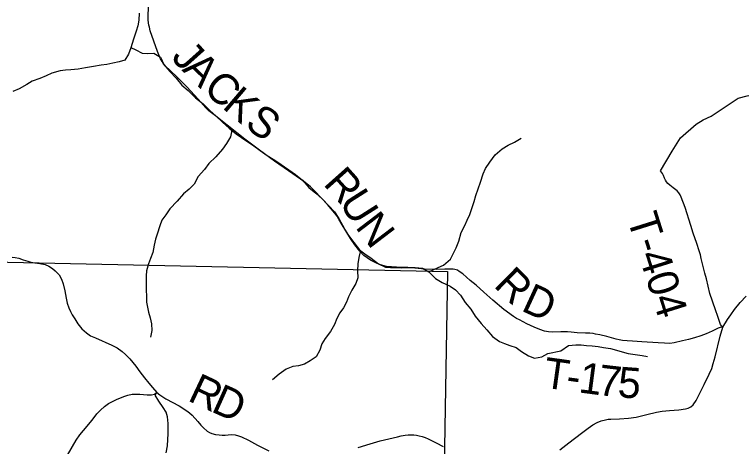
# Model space of a CAD drawing. Extents: x 0 to 34, y 0 to 22.
# Drawn here: x 25.254 to 26.601, y 19.296 to 20.097 of the extents above; entities that cross this region are included whole.
import ezdxf

# ---------------------------------------------------------------- set-up
doc = ezdxf.new("R2010")
doc.units = 0
for name, color, linetype in [('GM_X_Corporation', 7, 'Continuous'), ('GM_X_County_Road', 7, 'Continuous'), ('GM_X_County_Road_Text', 7, 'Continuous'), ('GM_X_Minor_River', 7, 'Continuous'), ('GM_X_State_Route', 7, 'Continuous'), ('GM_X_Township_Road', 7, 'Continuous'), ('GM_X_Township_Road_Text', 7, 'Continuous')]:
    doc.layers.add(name, color=color, linetype=linetype)

msp = doc.modelspace()

# ---------------------------------------------------------------- linework, layer by layer
at = {"layer": 'GM_X_Corporation'}
msp.add_lwpolyline([(25.037, 19.6422), (26.0559, 19.6207), (26.0385, 18.6067), (25.0268, 18.6245)], close=True, dxfattribs=at)
at = {"layer": 'GM_X_County_Road'}
for points in [[(25.2494, 19.6471), (25.2548, 19.6464), (25.2617, 19.6449), (25.2702, 19.6422), (25.2786, 19.6395), (25.2843, 19.6379), (25.2914, 19.6364), (25.301, 19.6355), (25.3105, 19.6335), (25.3175, 19.6306), (25.324, 19.6262), (25.3294, 19.6215), (25.3365, 19.6142), (25.341, 19.6063), (25.3438, 19.5979), (25.347, 19.5845), (25.3494, 19.5709), (25.3515, 19.5619), (25.3545, 19.5532), (25.3576, 19.5462), (25.3608, 19.54), (25.3655, 19.5325), (25.3715, 19.5232), (25.3788, 19.5142), (25.3874, 19.5066), (25.3948, 19.5015), (25.4041, 19.4973), (25.4344, 19.4841), (25.4439, 19.4788), (25.4533, 19.4722), (25.4595, 19.4668), (25.4675, 19.4587), (25.4785, 19.4449), (25.4859, 19.4348), (25.4944, 19.4233), (25.5029, 19.4132), (25.5097, 19.4052), (25.5177, 19.3965), (25.5229, 19.3918), (25.5286, 19.3879), (25.5344, 19.3847), (25.5587, 19.3714), (25.573, 19.3623), (25.5779, 19.3585), (25.5829, 19.354), (25.5932, 19.3426), (25.5993, 19.3355), (25.604, 19.3304), (25.6109, 19.3243), (25.6151, 19.3218), (25.6193, 19.3203), (25.6261, 19.3184), (25.6329, 19.3176), (25.6383, 19.3173), (25.6441, 19.3174), (25.6551, 19.3181), (25.6624, 19.3175), (25.6688, 19.3158), (25.6747, 19.3138), (25.6873, 19.3081), (25.7043, 19.2986), (25.7252, 19.2882)], [(25.8903, 19.2945), (25.9127, 19.3013), (25.9313, 19.3063), (25.9634, 19.3138), (25.9704, 19.3158), (25.9774, 19.317), (25.9832, 19.3178), (25.9889, 19.3178), (25.9935, 19.3176), (25.9983, 19.3169), (26.0036, 19.3159), (26.0092, 19.3146), (26.0147, 19.3128), (26.0204, 19.3103), (26.0278, 19.3069), (26.0351, 19.3027), (26.0478, 19.2961)]]:
    msp.add_lwpolyline(points, dxfattribs=at)
at = {"layer": 'GM_X_Minor_River'}
for points in [[(25.4851, 20.0991), (25.4843, 20.0866), (25.4821, 20.076), (25.4791, 20.0657), (25.4746, 20.0512), (25.4693, 20.0353), (25.4651, 20.0235), (25.458, 20.0121), (25.4477, 20.0094), (25.436, 20.0067), (25.425, 20.0043), (25.4143, 20.0028), (25.4003, 20.0008), (25.3855, 19.9978), (25.3719, 19.9954), (25.3582, 19.9943), (25.3483, 19.9935), (25.3385, 19.9923), (25.3233, 19.9884), (25.3123, 19.9831), (25.3006, 19.9785), (25.2865, 19.9731), (25.2767, 19.9674), (25.2623, 19.959), (25.2509, 19.954)], [(25.4694, 20.0355), (25.4784, 20.0311), (25.4902, 20.0251), (25.4997, 20.0247), (25.5122, 20.0251), (25.5243, 20.0176), (25.5308, 20.0043), (25.5419, 19.9914), (25.5533, 19.9789), (25.5639, 19.9661), (25.5757, 19.9558), (25.5894, 19.9422), (25.6031, 19.9312), (25.6157, 19.9187), (25.6274, 19.9085), (25.6392, 19.8975), (25.6518, 19.8862), (25.6643, 19.8756), (25.6746, 19.8691), (25.6845, 19.8623), (25.697, 19.8533), (25.7092, 19.8446), (25.7217, 19.8355), (25.7362, 19.8268), (25.748, 19.8188), (25.762, 19.809), (25.7742, 19.8003), (25.7875, 19.7897), (25.7993, 19.7765), (25.8118, 19.7659), (25.824, 19.7553), (25.8362, 19.7424), (25.8465, 19.7314), (25.8548, 19.7189), (25.8613, 19.7064), (25.8663, 19.6969), (25.8728, 19.6874), (25.8823, 19.6741), (25.8933, 19.6605), (25.9028, 19.6533), (25.9146, 19.645), (25.9279, 19.6344), (25.9412, 19.6283), (25.9507, 19.628), (25.9609, 19.628), (25.9704, 19.6273), (25.9833, 19.6277), (25.9962, 19.6277), (26.0095, 19.6266), (26.0217, 19.6198), (26.0339, 19.6073), (26.046, 19.5998), (26.0608, 19.593), (26.0711, 19.5866), (26.0802, 19.5767), (26.089, 19.5631), (26.0993, 19.5509), (26.1073, 19.538), (26.1183, 19.524), (26.1286, 19.5123), (26.1396, 19.4997), (26.1522, 19.4907), (26.1617, 19.4873), (26.1716, 19.4835), (26.1833, 19.4797), (26.1928, 19.4722), (26.2058, 19.4642), (26.2175, 19.4601), (26.2308, 19.4624), (26.2422, 19.4685), (26.2657, 19.4732)], [(25.6565, 19.8822), (25.6541, 19.8702), (25.6469, 19.8577), (25.639, 19.847), (25.6269, 19.8333), (25.6136, 19.8207), (25.6057, 19.8093), (25.5943, 19.7967), (25.5868, 19.7826), (25.5777, 19.7731), (25.5667, 19.7647), (25.5554, 19.751), (25.5418, 19.7365), (25.5342, 19.7258), (25.527, 19.7159), (25.5232, 19.7049), (25.5183, 19.69), (25.515, 19.6802), (25.5127, 19.6691), (25.5101, 19.6558), (25.5056, 19.6444), (25.5022, 19.6345), (25.4984, 19.622), (25.4977, 19.6125), (25.4978, 19.5859), (25.4982, 19.5745), (25.4986, 19.5638), (25.5001, 19.5543), (25.502, 19.5448), (25.5051, 19.5346), (25.5074, 19.5232), (25.5082, 19.511), (25.5056, 19.4985)], [(26.0217, 19.6198), (26.0387, 19.6279), (26.0486, 19.6321), (26.0615, 19.6432), (26.0668, 19.6534), (26.072, 19.6641), (26.0769, 19.677), (26.0814, 19.693), (26.0882, 19.7059), (26.0924, 19.7158), (26.0973, 19.7261), (26.1003, 19.7356), (26.1052, 19.7501), (26.1086, 19.7615), (26.1127, 19.774), (26.1169, 19.7858), (26.1221, 19.8014), (26.1267, 19.8113), (26.1342, 19.8231), (26.1444, 19.8365), (26.1573, 19.8479), (26.1687, 19.8548), (26.1801, 19.8601), (26.1926, 19.8678)], [(25.8946, 19.6595), (25.8918, 19.6464), (25.89, 19.6346), (25.8893, 19.6217), (25.8897, 19.6088), (25.8863, 19.5981), (25.8791, 19.5859), (25.8727, 19.5734), (25.8689, 19.5639), (25.8633, 19.5532), (25.8568, 19.5437), (25.8508, 19.5334), (25.8466, 19.522), (25.8395, 19.509), (25.8293, 19.4961), (25.8232, 19.4862), (25.8198, 19.4748), (25.8126, 19.4626), (25.8013, 19.4546), (25.7914, 19.4488), (25.7801, 19.4458), (25.7694, 19.4442), (25.7573, 19.4396), (25.7444, 19.4301), (25.7319, 19.4198)], [(26.2657, 19.4732), (26.28, 19.4832), (26.2936, 19.4848), (26.3038, 19.4846), (26.3133, 19.4832), (26.3239, 19.4829), (26.3349, 19.4812), (26.3451, 19.4798), (26.358, 19.4777), (26.369, 19.4748), (26.3796, 19.4715), (26.3906, 19.4686), (26.4039, 19.4665), (26.4164, 19.4648), (26.4266, 19.463)]]:
    msp.add_lwpolyline(points, dxfattribs=at)
at = {"layer": 'GM_X_State_Route'}
msp.add_lwpolyline([(26.264, 19.2901), (26.2805, 19.3029), (26.3045, 19.3206), (26.3166, 19.33), (26.3251, 19.336), (26.3332, 19.3406), (26.3408, 19.3436), (26.3486, 19.3457), (26.3539, 19.3465), (26.3589, 19.3468), (26.3746, 19.3471), (26.3916, 19.3484), (26.4057, 19.3506), (26.4251, 19.3554), (26.443, 19.3596), (26.4539, 19.3614), (26.467, 19.3629), (26.4845, 19.3643), (26.4969, 19.3657), (26.502, 19.3671), (26.507, 19.3696), (26.511, 19.3732), (26.5165, 19.3812), (26.5318, 19.4113), (26.5408, 19.43), (26.5454, 19.4408), (26.5481, 19.4497), (26.5517, 19.4625), (26.5609, 19.5005), (26.566, 19.517), (26.5749, 19.5314), (26.5807, 19.5404), (26.5875, 19.5499), (26.598, 19.5628), (26.6091, 19.5745)], dxfattribs=at)
at = {"layer": 'GM_X_Township_Road'}
for points in [[(26.566, 19.517), (26.5612, 19.5168), (26.5572, 19.5156), (26.5464, 19.51), (26.5407, 19.5073), (26.5352, 19.5049), (26.5253, 19.5013), (26.5135, 19.4978), (26.5024, 19.4947), (26.4915, 19.4921), (26.476, 19.4883), (26.4677, 19.4873), (26.4583, 19.4876), (26.4464, 19.4885), (26.4158, 19.4902), (26.3987, 19.4911), (26.3887, 19.492), (26.3802, 19.4928), (26.3738, 19.4938), (26.3682, 19.4952), (26.3511, 19.4997), (26.338, 19.5029), (26.3303, 19.5045), (26.3256, 19.5054), (26.32, 19.506), (26.3116, 19.5063), (26.2965, 19.5069), (26.2853, 19.508), (26.2783, 19.5085), (26.2662, 19.5085), (26.2506, 19.5079), (26.243, 19.5084), (26.2357, 19.51), (26.2273, 19.5128), (26.2167, 19.5172), (26.203, 19.5237), (26.1895, 19.5307), (26.1837, 19.5336), (26.1783, 19.5371), (26.1606, 19.55), (26.1401, 19.5672), (26.1234, 19.5822), (26.1091, 19.5951), (26.0982, 19.6039), (26.0845, 19.6159), (26.0779, 19.6208), (26.0743, 19.6228), (26.0699, 19.6243), (26.0663, 19.625), (26.0625, 19.6251), (26.0509, 19.6248), (26.0355, 19.6239), (26.0137, 19.6246), (26.0018, 19.6258), (25.9823, 19.6279), (25.9617, 19.6287), (25.9429, 19.63), (25.9319, 19.6329), (25.9242, 19.6361), (25.9182, 19.6389), (25.9135, 19.6418), (25.9075, 19.6458), (25.9013, 19.6504), (25.8936, 19.6581), (25.8844, 19.6699), (25.8766, 19.6815), (25.8695, 19.6928), (25.8591, 19.7099), (25.8547, 19.7177), (25.8516, 19.7229), (25.8475, 19.7289), (25.834, 19.7446), (25.8104, 19.7691), (25.8021, 19.7772), (25.7925, 19.7853), (25.7836, 19.7919), (25.7614, 19.8073), (25.7358, 19.8251), (25.7076, 19.8452), (25.6803, 19.866), (25.6477, 19.8916), (25.6264, 19.9089), (25.614, 19.9184), (25.6084, 19.924), (25.5941, 19.9398), (25.5802, 19.9554), (25.5739, 19.9619), (25.556, 19.9801), (25.542, 19.993), (25.5331, 20.0016), (25.5301, 20.0055), (25.5273, 20.0097), (25.5244, 20.0149), (25.5225, 20.0189), (25.519, 20.0286), (25.5122, 20.0475), (25.5055, 20.0664), (25.5037, 20.0732), (25.5027, 20.0773), (25.5012, 20.0865), (25.5013, 20.0935), (25.5021, 20.1102)], [(26.5499, 19.9122), (26.5945, 19.9421), (26.6112, 19.9463), (26.6297, 19.9496), (26.6581, 19.9549), (26.6747, 19.9585), (26.6814, 19.96), (26.6906, 19.9628), (26.7039, 19.9693), (26.711, 19.9751)], [(26.566, 19.517), (26.5634, 19.5195), (26.5617, 19.5222), (26.5571, 19.5369), (26.5528, 19.5497), (26.5422, 19.5797), (26.5357, 19.6067), (26.533, 19.6177), (26.5295, 19.6299), (26.5259, 19.6446), (26.5245, 19.6515), (26.5223, 19.659), (26.518, 19.6722), (26.5113, 19.6913), (26.5069, 19.7055), (26.4962, 19.7393), (26.4891, 19.7584), (26.487, 19.7625), (26.4846, 19.7662), (26.4812, 19.7698), (26.4742, 19.7757), (26.4682, 19.7803), (26.4643, 19.7839), (26.462, 19.7866), (26.4598, 19.79), (26.4578, 19.7938), (26.4559, 19.7985), (26.4542, 19.8021), (26.4526, 19.8044), (26.4507, 19.8068), (26.4722, 19.8438), (26.4874, 19.8685), (26.5168, 19.8939), (26.5294, 19.9014), (26.5446, 19.9086), (26.5499, 19.9122)], [(25.3518, 19.2803), (25.3683, 19.3081), (25.3748, 19.3178), (25.3816, 19.3259), (25.3975, 19.345), (25.4064, 19.3565), (25.4133, 19.3637), (25.4204, 19.3704), (25.4283, 19.3759), (25.4427, 19.3833), (25.4563, 19.389), (25.4636, 19.3915), (25.4716, 19.3931), (25.4859, 19.3932), (25.4996, 19.392), (25.5077, 19.3917), (25.5131, 19.3931), (25.5177, 19.3965)], [(25.535, 19.2845), (25.5374, 19.2974), (25.5383, 19.3201), (25.5384, 19.3389), (25.5371, 19.3509), (25.535, 19.3597), (25.5292, 19.3685), (25.5212, 19.3804), (25.5144, 19.3913), (25.5177, 19.3965)]]:
    msp.add_lwpolyline(points, dxfattribs=at)

# ---------------------------------------------------------------- texts
at = {"layer": 'GM_X_County_Road_Text'}
for s, rotation, p in [('R', 334.7843, (25.5726, 19.3821)), ('D', 335.969, (25.616, 19.3617))]:
    msp.add_text(s, height=0.0568, rotation=rotation, dxfattribs=at).set_placement(p)
at = {"layer": 'GM_X_Township_Road_Text'}
for s, height, rotation, p in [('J', 0.0568, 311.7674, (25.5425, 20.0165)), ('A', 0.0568, 315.2962, (25.5629, 19.9938)), ('C', 0.0568, 318.6059, (25.6011, 19.9562)), ('K', 0.0568, 319.6153, (25.6369, 19.9246)), ('S', 0.0568, 323.4722, (25.6783, 19.8896)), ('R', 0.0568, 311.7444, (25.8243, 19.7823)), ('U', 0.0568, 302.417, (25.8539, 19.7495)), ('N', 0.0568, 307.3655, (25.8838, 19.7029)), ('T-404', 0.05682, 287.4332, (26.3883, 19.7196)), ('R', 0.0568, 315.5133, (26.1399, 19.5934)), ('D', 0.0568, 335.336, (26.1905, 19.5488)), ('T', 0.0568, 352.0893, (26.2316, 19.4057)), ('1', 0.0568, 352.5077, (26.2973, 19.3966)), ('7', 0.0568, 353.359, (26.3329, 19.3919)), ('5', 0.0568, 355.6513, (26.3701, 19.3877)), ('-', 0.0568, 352.1762, (26.2738, 19.3998))]:
    msp.add_text(s, height=height, rotation=rotation, dxfattribs=at).set_placement(p)

doc.saveas('drawing.dxf')
